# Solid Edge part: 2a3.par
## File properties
Author: edge
Template: jis part.par
Last saved by: edge
Revision: 21
Application: Solid Edge
Accuracy: 0.990
文書内容のタイプ: 0
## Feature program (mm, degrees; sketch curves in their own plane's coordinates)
sketch for "unnamed Protrusion 1" plane through (0, 0, 0) normal (1, 0, 0) x-axis (0, 1, 0)
  line (0, 0) -> (-80, 0)
  line (-80, 0) -> (-80, 180)
  line (-80, 180) -> (0, 180)
  line (0, 180) -> (0, 0)
extrude "unnamed Protrusion 1" add finite 160 symmetric
thinwall "Thinwall_1"  Thickness = 20 mm
sketch for "unnamed Cutout 1" plane through (0, 0, 0) normal (0, -1, 0) x-axis (1, 0, 0)
  circle centre (0, 120) radius 27.5
extrude "unnamed Cutout 1" cut through
sketch for "unnamed Cutout 2" #1 plane through (0, 0, 0) normal (0, -1, 0) x-axis (1, 0, 0)
sketch for "unnamed Cutout 2" #2 plane through (0, 0, 0) normal (0, -1, 0) x-axis (1, 0, 0)
  circle centre (-50, 120) radius 6
extrude "unnamed Cutout 2" cut through along +normal
sketch for "unnamed Cutout 3" #1 plane through (0, 0, 0) normal (0, 0, 1) x-axis (1, 0, 0)
sketch for "unnamed Cutout 3" #2 plane through (0, 0, 0) normal (0, 0, 1) x-axis (1, 0, 0)
extrude "unnamed Cutout 3" cut through along +normal
chamfer "Chamfer_1" setback 5
chamfer "Chamfer_2" setback 5
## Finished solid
Body 1: solid body, 17 faces, 40 edges, 20 vertices.
  Faces by surface: plane 12, cylinder 5
  Edges by curve: line 30, circle 10
Bounding box of the edges (mm): 160.000 x 80.000 x 180.000, from (-80, -80, 0) to (80, 0, 180).
Cylindrical faces by radius (mm): R6 x2, R7.5 x2, R27.5 x1
Planar faces by outward normal: +x 1, +y 1, +z 2, -x 1, -y 2, -z 1, oblique 4
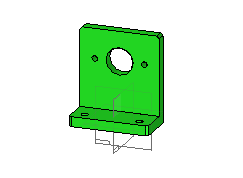
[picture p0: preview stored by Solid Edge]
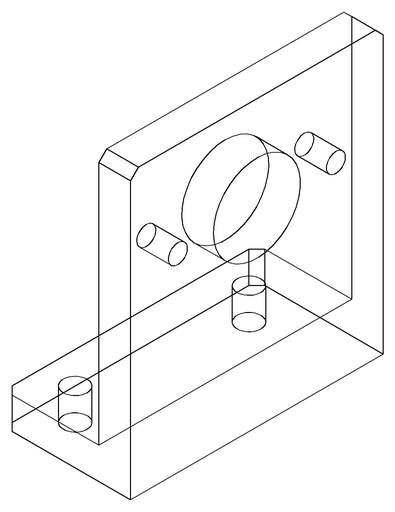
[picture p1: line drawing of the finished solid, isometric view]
